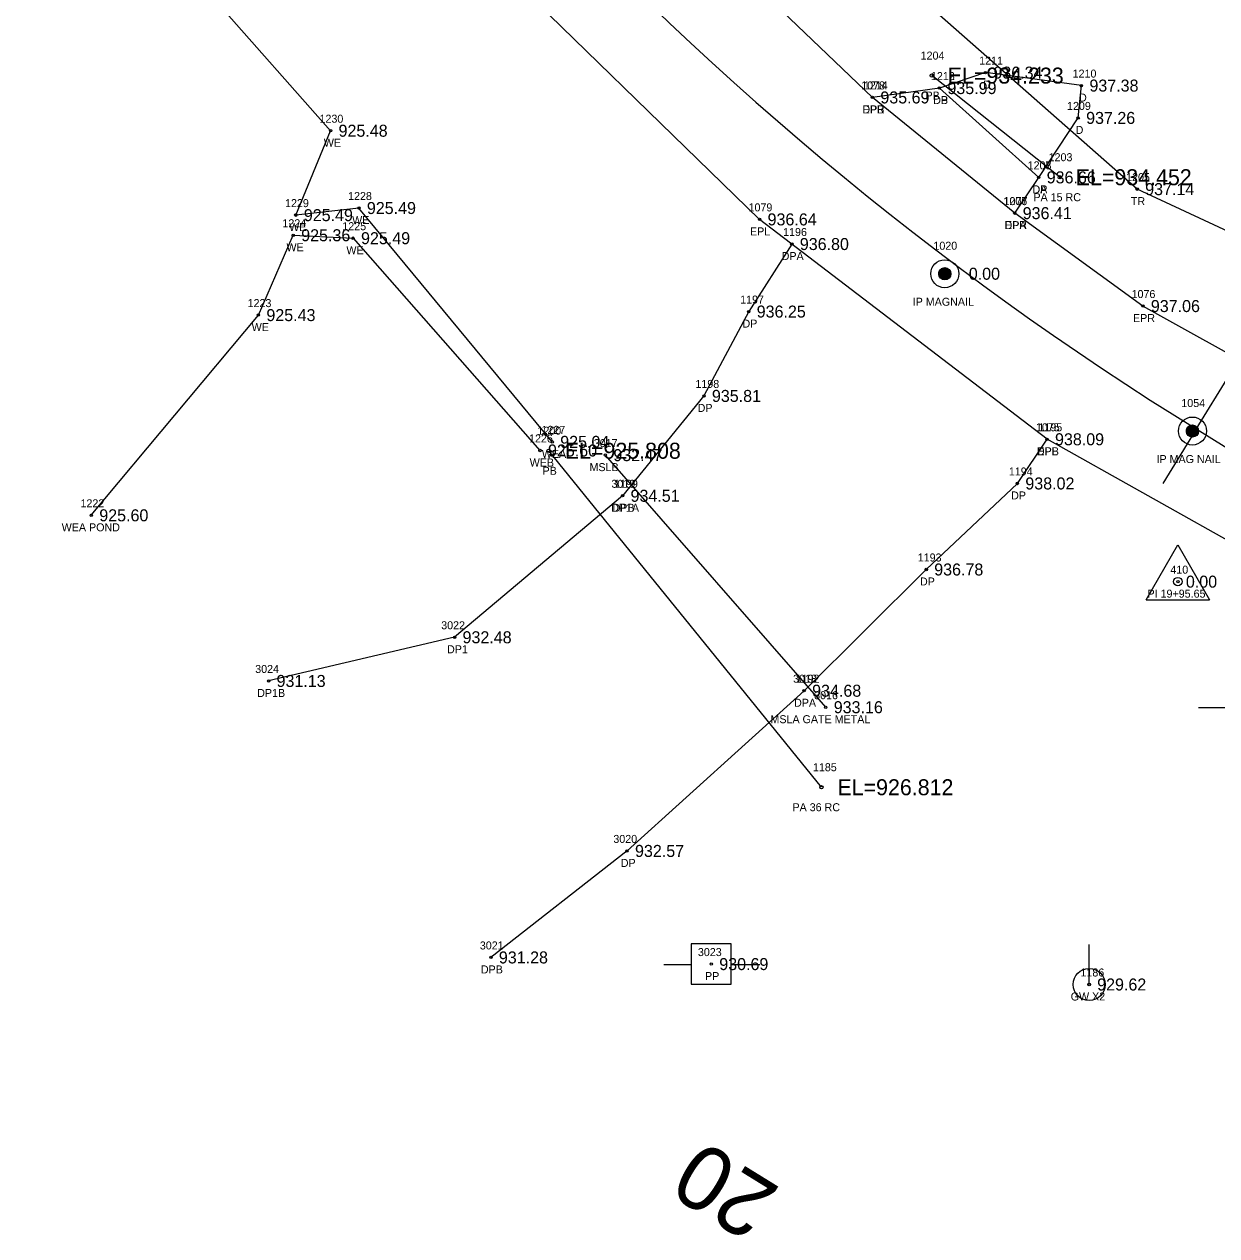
# Model space of a CAD drawing. Extents: x 1528109 to 1531398, y 1157799 to 1162548.
# Drawn here: x 1529980.7 to 1530129.8, y 1159115.4 to 1159266.8 of the extents above; entities that cross this region are included whole.
import ezdxf

# ---------------------------------------------------------------- set-up
doc = ezdxf.new("R2010")
doc.units = 0
for name, color, linetype in [('RD_EX_DR_Pipe', 7, 'Continuous'), ('RD_EX_DR_Pipe_txCode', 7, 'Continuous'), ('RD_EX_Driveway', 7, 'Continuous'), ('RD_EX_Driveway_txCode', 7, 'Continuous'), ('RD_EX_DV_Prop_txCode', 7, 'Continuous'), ('RD_EX_DV_PropPin', 7, 'Continuous'), ('RD_EX_H2O', 7, 'Continuous'), ('RD_EX_H2O_txCode', 7, 'Continuous'), ('RD_EX_Misc', 7, 'Continuous'), ('RD_EX_Misc_txCode', 7, 'Continuous'), ('RD_EX_Road', 7, 'Continuous'), ('RD_EX_Road_txCode', 7, 'Continuous'), ('RD_EX_TX_Driveway_ELEV', 7, 'Continuous'), ('RD_EX_TX_DV_Prop_ELEV', 7, 'Continuous'), ('RD_EX_TX_H2O_ELEV', 7, 'Continuous'), ('RD_EX_TX_Misc_ELEV', 7, 'Continuous'), ('RD_EX_TX_Road_ELEV', 7, 'Continuous'), ('RD_EX_TX_UT_ELEV', 7, 'Continuous'), ('RD_EX_TX_VEG_ELEV', 7, 'Continuous'), ('RD_EX_UT', 7, 'Continuous'), ('RD_EX_UT_txCode', 7, 'Continuous'), ('RD_EX_VEG', 7, 'Continuous'), ('RD_EX_VEG_txCode', 7, 'Continuous'), ('RD_HC_Cl', 7, 'Continuous'), ('RD_HC_Data', 7, 'Continuous'), ('RD_HC_Data_Tic', 7, 'Continuous'), ('RD_HC_Survey_ELEV', 7, 'Continuous'), ('RD_HC_TX_Sta50', 7, 'Continuous'), ('RD_HC_txCode', 7, 'Continuous'), ('RD_SMD_Locator', 7, 'Continuous'), ('RD_TX_Pipe_ElevEX', 7, 'Continuous')]:
    doc.layers.add(name, color=color, linetype=linetype)

msp = doc.modelspace()

# ---------------------------------------------------------------- linework, layer by layer
at = {"layer": 'RD_EX_DR_Pipe'}
for p, q in [((1530110.19, 1159247.64), (1530094.19, 1159260.34)), ((1530080.4, 1159171.41), (1530046.32, 1159213.46))]:
    msp.add_line(p, q, dxfattribs=at)
at = {"layer": 'RD_EX_Driveway'}
for points in [[(1530107.56, 1159247.62), (1530112.49, 1159255.05), (1530112.9, 1159259.09), (1530100.9, 1159260.71), (1530095.15, 1159258.78)], [(1530104.56, 1159243.15), (1530107.56, 1159247.62), (1530095.15, 1159258.78), (1530086.77, 1159257.61)], [(1530076.7, 1159239.29), (1530071.31, 1159230.85), (1530065.71, 1159220.31), (1530055.54, 1159207.83)], [(1530078.24, 1159183.47), (1530093.5, 1159198.62), (1530104.89, 1159209.37), (1530108.6, 1159214.89)], [(1530055.54, 1159207.83), (1530034.54, 1159190.15), (1530011.29, 1159184.69)], [(1530078.24, 1159183.47), (1530056.1, 1159163.45), (1530039.08, 1159150.14)]]:
    msp.add_lwpolyline(points, dxfattribs=at)
at = {"layer": 'RD_EX_DV_PropPin'}
for p, q in [((1530095.61, 1159234.85), (1530095.61, 1159236.31)), ((1530095.65, 1159234.84), (1530095.65, 1159236.32)), ((1530095.68, 1159234.83), (1530095.68, 1159236.33)), ((1530095.72, 1159234.83), (1530095.72, 1159236.33)), ((1530095.75, 1159234.82), (1530095.75, 1159236.34)), ((1530095.79, 1159234.82), (1530095.79, 1159236.34)), ((1530095.82, 1159234.82), (1530095.82, 1159236.34)), ((1530095.86, 1159234.82), (1530095.86, 1159236.34)), ((1530095.89, 1159234.82), (1530095.89, 1159236.34)), ((1530095.93, 1159234.83), (1530095.93, 1159236.33)), ((1530095.96, 1159234.83), (1530095.96, 1159236.33)), ((1530096, 1159234.84), (1530096, 1159236.32)), ((1530096.03, 1159234.85), (1530096.03, 1159236.31)), ((1530095.09, 1159235.38), (1530095.09, 1159235.78)), ((1530095.12, 1159235.28), (1530095.12, 1159235.88)), ((1530095.16, 1159235.21), (1530095.16, 1159235.95)), ((1530095.19, 1159235.15), (1530095.19, 1159236.01)), ((1530095.23, 1159235.11), (1530095.23, 1159236.05)), ((1530095.26, 1159235.07), (1530095.26, 1159236.1)), ((1530095.3, 1159235.03), (1530095.3, 1159236.13)), ((1530095.33, 1159235), (1530095.33, 1159236.16)), ((1530095.37, 1159234.97), (1530095.37, 1159236.19)), ((1530095.4, 1159234.95), (1530095.4, 1159236.21)), ((1530095.44, 1159234.92), (1530095.44, 1159236.24)), ((1530095.47, 1159234.9), (1530095.47, 1159236.26)), ((1530095.51, 1159234.89), (1530095.51, 1159236.27)), ((1530095.54, 1159234.87), (1530095.54, 1159236.29)), ((1530095.58, 1159234.86), (1530095.58, 1159236.3)), ((1530096.07, 1159234.86), (1530096.07, 1159236.3)), ((1530096.1, 1159234.87), (1530096.1, 1159236.29)), ((1530096.14, 1159234.89), (1530096.14, 1159236.27)), ((1530096.17, 1159234.9), (1530096.17, 1159236.26)), ((1530096.21, 1159234.92), (1530096.21, 1159236.24)), ((1530096.24, 1159234.95), (1530096.24, 1159236.21)), ((1530096.28, 1159234.97), (1530096.28, 1159236.19)), ((1530096.31, 1159235), (1530096.31, 1159236.16)), ((1530096.35, 1159235.03), (1530096.35, 1159236.13)), ((1530096.38, 1159235.07), (1530096.38, 1159236.1)), ((1530096.42, 1159235.11), (1530096.42, 1159236.05)), ((1530096.45, 1159235.15), (1530096.45, 1159236.01)), ((1530096.49, 1159235.21), (1530096.49, 1159235.95)), ((1530096.52, 1159235.28), (1530096.52, 1159235.88)), ((1530096.56, 1159235.38), (1530096.56, 1159235.78)), ((1530126.49, 1159215.21), (1530126.49, 1159216.63)), ((1530126.53, 1159215.2), (1530126.53, 1159216.64)), ((1530126.56, 1159215.19), (1530126.56, 1159216.65)), ((1530126.6, 1159215.18), (1530126.6, 1159216.66)), ((1530126.64, 1159215.17), (1530126.64, 1159216.67)), ((1530126.67, 1159215.17), (1530126.67, 1159216.67)), ((1530126.71, 1159215.16), (1530126.71, 1159216.68)), ((1530126.74, 1159215.16), (1530126.74, 1159216.68)), ((1530126.78, 1159215.16), (1530126.78, 1159216.68)), ((1530126.81, 1159215.16), (1530126.81, 1159216.68)), ((1530126.85, 1159215.16), (1530126.85, 1159216.68)), ((1530126.88, 1159215.17), (1530126.88, 1159216.67)), ((1530126.92, 1159215.17), (1530126.92, 1159216.67)), ((1530126.95, 1159215.18), (1530126.95, 1159216.66)), ((1530126.99, 1159215.19), (1530126.99, 1159216.65)), ((1530127.02, 1159215.2), (1530127.02, 1159216.64)), ((1530127.06, 1159215.21), (1530127.06, 1159216.63)), ((1530126.04, 1159215.72), (1530126.04, 1159216.12)), ((1530126.07, 1159215.62), (1530126.07, 1159216.22)), ((1530126.11, 1159215.55), (1530126.11, 1159216.29)), ((1530126.14, 1159215.49), (1530126.14, 1159216.35)), ((1530126.18, 1159215.45), (1530126.18, 1159216.39)), ((1530126.21, 1159215.4), (1530126.21, 1159216.44)), ((1530126.25, 1159215.37), (1530126.25, 1159216.47)), ((1530126.28, 1159215.34), (1530126.28, 1159216.5)), ((1530126.32, 1159215.31), (1530126.32, 1159216.53)), ((1530126.35, 1159215.29), (1530126.35, 1159216.55)), ((1530126.39, 1159215.26), (1530126.39, 1159216.58)), ((1530126.42, 1159215.24), (1530126.42, 1159216.6)), ((1530126.46, 1159215.23), (1530126.46, 1159216.61)), ((1530127.09, 1159215.23), (1530127.09, 1159216.61)), ((1530127.13, 1159215.24), (1530127.13, 1159216.6)), ((1530127.16, 1159215.26), (1530127.16, 1159216.58)), ((1530127.2, 1159215.29), (1530127.2, 1159216.55)), ((1530127.23, 1159215.31), (1530127.23, 1159216.53)), ((1530127.27, 1159215.34), (1530127.27, 1159216.5)), ((1530127.3, 1159215.37), (1530127.3, 1159216.47)), ((1530127.34, 1159215.4), (1530127.34, 1159216.44)), ((1530127.37, 1159215.45), (1530127.37, 1159216.39)), ((1530127.41, 1159215.49), (1530127.41, 1159216.35)), ((1530127.44, 1159215.55), (1530127.44, 1159216.29)), ((1530127.48, 1159215.62), (1530127.48, 1159216.22)), ((1530127.51, 1159215.72), (1530127.51, 1159216.12))]:
    msp.add_line(p, q, dxfattribs=at)
for centre, radius in [((1530095.82, 1159235.58), 1.75), ((1530095.82, 1159235.58), 0.761), ((1530126.78, 1159215.92), 1.75), ((1530126.78, 1159215.92), 0.761)]:
    msp.add_circle(centre, radius, dxfattribs=at)
at = {"layer": 'RD_EX_H2O'}
for points in [[(1530046.75, 1159214.57), (1530022.58, 1159243.79), (1530014.7, 1159242.9), (1530019.04, 1159253.45), (1530004.76, 1159269.6), (1529985.6, 1159289.95), (1529959.08, 1159302.6), (1529953.51, 1159302.02), (1529918.95, 1159284.91)], [(1529989.13, 1159205.39), (1530010.02, 1159230.41), (1530014.37, 1159240.39), (1530021.85, 1159240.02), (1530045.22, 1159213.49)]]:
    msp.add_lwpolyline(points, dxfattribs=at)
at = {"layer": 'RD_EX_Misc'}
msp.add_line((1530080.94, 1159181.41), (1530053.39, 1159212.91), dxfattribs=at)
at = {"layer": 'RD_EX_Road'}
for points in [[(1530337.52, 1159156.44), (1530294.13, 1159166.93), (1530250.93, 1159177.7), (1530204.42, 1159191.5), (1530168.45, 1159204.97), (1530120.58, 1159231.54), (1530104.56, 1159243.15), (1530086.77, 1159257.61), (1530051.98, 1159290.88), (1530019.2, 1159326.18), (1529978.15, 1159378.31), (1529959.68, 1159408.2), (1529942.81, 1159442.34), (1529934.79, 1159460.88), (1529923.22, 1159491.09), (1529910.46, 1159527.95), (1529895.99, 1159570.93), (1529881.69, 1159613.98), (1529856.28, 1159690.67), (1529839.74, 1159739.71), (1529819.57, 1159800.04), (1529788.95, 1159890.99)], [(1530332.28, 1159136.67), (1530288.96, 1159147.06), (1530245.68, 1159158), (1530197.52, 1159172.18), (1530159.1, 1159186.57), (1530108.6, 1159214.89), (1530072.67, 1159242.37), (1530037.12, 1159276.96), (1530005.21, 1159311.5), (1529961.59, 1159366.88), (1529941.79, 1159398.29), (1529924.06, 1159434.11), (1529903.77, 1159484.39), (1529891.44, 1159520.8), (1529876.79, 1159564.7), (1529862.9, 1159606.82), (1529836.94, 1159684.29), (1529820.66, 1159733.09), (1529800.02, 1159794.4), (1529769.54, 1159884.46)]]:
    msp.add_lwpolyline(points, dxfattribs=at)
at = {"layer": 'RD_EX_UT'}
for p, q in [((1530127.55, 1159181.37), (1530131.02, 1159181.37)), ((1530069.12, 1159151.82), (1530064.12, 1159151.82)), ((1530064.12, 1159151.82), (1530064.12, 1159146.82)), ((1530069.12, 1159146.82), (1530069.12, 1159151.82)), ((1530113.87, 1159146.76), (1530113.87, 1159151.76)), ((1530060.69, 1159149.26), (1530064.16, 1159149.26)), ((1530069.05, 1159149.26), (1530072.69, 1159149.26)), ((1530064.12, 1159146.82), (1530069.12, 1159146.82))]:
    msp.add_line(p, q, dxfattribs=at)
msp.add_circle((1530113.87, 1159146.76), 2, dxfattribs=at)
at = {"layer": 'RD_EX_VEG'}
msp.add_lwpolyline([(1530334.72, 1159172.48), (1530202.71, 1159207.61), (1530119.87, 1159246.15), (1530082.28, 1159279.25), (1530129.08, 1159268.9), (1530183.31, 1159274.22)], dxfattribs=at)
at = {"layer": 'RD_HC_Cl'}
msp.add_arc((1530338.63, 1159558.58), 402.39, 222.8065, 256.0174, dxfattribs=at)
at = {"layer": 'RD_HC_Data'}
for p, q in [((1530120.99, 1159194.81), (1530124.96, 1159201.69)), ((1530124.96, 1159201.69), (1530128.93, 1159194.81)), ((1530120.99, 1159194.81), (1530128.93, 1159194.81))]:
    msp.add_line(p, q, dxfattribs=at)
msp.add_circle((1530124.96, 1159197.1), 0.529, dxfattribs=at)
at = {"layer": 'RD_HC_Data_Tic'}
for q in [(1530131.46, 1159222.98), (1530123.06, 1159209.37)]:
    msp.add_line((1530127.26, 1159216.17), q, dxfattribs=at)
at = {"layer": 'RD_SMD_Locator'}
for centre, radius in [((1530094.19, 1159260.34), 0.2), ((1530100.9, 1159260.71), 0.15), ((1530112.9, 1159259.09), 0.15), ((1530086.77, 1159257.61), 0.15), ((1530086.77, 1159257.61), 0.15), ((1530095.15, 1159258.78), 0.15), ((1530095.15, 1159258.78), 0.15), ((1530112.49, 1159255.05), 0.15), ((1530019.04, 1159253.45), 0.15), ((1530107.56, 1159247.62), 0.15), ((1530107.56, 1159247.62), 0.15), ((1530110.19, 1159247.64), 0.2), ((1530119.87, 1159246.15), 0.15), ((1530022.58, 1159243.79), 0.15), ((1530014.7, 1159242.9), 0.15), ((1530072.67, 1159242.37), 0.15), ((1530104.56, 1159243.15), 0.15), ((1530104.56, 1159243.15), 0.15), ((1530014.37, 1159240.39), 0.15), ((1530021.85, 1159240.02), 0.15), ((1530076.7, 1159239.29), 0.15), ((1530095.82, 1159235.58), 0.15), ((1530010.02, 1159230.41), 0.15), ((1530071.31, 1159230.85), 0.15), ((1530120.58, 1159231.54), 0.15), ((1530065.71, 1159220.31), 0.15), ((1530126.78, 1159215.92), 0.15), ((1530045.22, 1159213.49), 0.15), ((1530046.32, 1159213.46), 0.2), ((1530046.75, 1159214.57), 0.15), ((1530108.6, 1159214.89), 0.15), ((1530108.6, 1159214.89), 0.15), ((1530053.39, 1159212.91), 0.15), ((1530104.89, 1159209.37), 0.15), ((1530055.54, 1159207.83), 0.15), ((1530055.54, 1159207.83), 0.15), ((1529989.13, 1159205.39), 0.15), ((1530093.5, 1159198.62), 0.15), ((1530124.96, 1159197.1), 0.15), ((1530034.54, 1159190.15), 0.15), ((1530011.29, 1159184.69), 0.15), ((1530078.24, 1159183.47), 0.15), ((1530078.24, 1159183.47), 0.15), ((1530080.94, 1159181.41), 0.15), ((1530080.4, 1159171.41), 0.2), ((1530056.1, 1159163.45), 0.15), ((1530039.08, 1159150.14), 0.15), ((1530066.63, 1159149.31), 0.15), ((1530113.87, 1159146.76), 0.15)]:
    msp.add_circle(centre, radius, dxfattribs=at)

# ---------------------------------------------------------------- texts
at = {"layer": 'RD_EX_DR_Pipe_txCode'}
for s, p in [('1204', (1530092.8, 1159262.34)), ('PB', (1530093.41, 1159257.34)), ('1203', (1530108.8, 1159249.64)), ('PA 15 RC', (1530106.9, 1159244.64)), ('1200', (1530044.9, 1159215.46)), ('PB', (1530045.54, 1159210.46)), ('1185', (1530079.34, 1159173.41)), ('PA 36 RC', (1530076.78, 1159168.41))]:
    msp.add_text(s, height=1, dxfattribs=at).set_placement(p)
at = {"layer": 'RD_EX_Driveway_txCode'}
for s, p in [('1211', (1530100.12, 1159261.71)), ('1212', (1530094.09, 1159259.78)), ('1213', (1530094.09, 1159259.78)), ('1210', (1530111.8, 1159260.09)), ('1214', (1530085.7, 1159258.61)), ('D', (1530100.6, 1159258.71)), ('DB', (1530094.37, 1159256.78)), ('DP', (1530094.37, 1159256.78)), ('D', (1530112.6, 1159257.09)), ('DPB', (1530085.52, 1159255.61)), ('1209', (1530111.1, 1159256.05)), ('D', (1530112.18, 1159253.05)), ('1207', (1530106.18, 1159248.62)), ('1208', (1530106.18, 1159248.62)), ('DA', (1530106.77, 1159245.62)), ('DP', (1530106.79, 1159245.62)), ('1206', (1530103.15, 1159244.15)), ('1196', (1530075.61, 1159240.29)), ('DPA', (1530103.3, 1159241.15)), ('DPA', (1530075.43, 1159237.29)), ('1197', (1530070.24, 1159231.85)), ('DP', (1530070.53, 1159228.85)), ('1198', (1530064.65, 1159221.31)), ('DP', (1530064.93, 1159218.31)), ('1195', (1530107.53, 1159215.89)), ('DPB', (1530107.34, 1159212.89)), ('1194', (1530103.83, 1159210.37)), ('3019', (1530054.15, 1159208.83)), ('1199', (1530054.48, 1159208.83)), ('DP', (1530104.11, 1159207.37)), ('DP1A', (1530054.11, 1159205.83)), ('DPB', (1530054.29, 1159205.83)), ('1193', (1530092.44, 1159199.62)), ('DP', (1530092.72, 1159196.62)), ('3022', (1530032.87, 1159191.15)), ('DP1', (1530033.6, 1159188.15)), ('3024', (1530009.62, 1159185.69)), ('3018', (1530076.86, 1159184.47)), ('1192', (1530077.18, 1159184.47)), ('DP1B', (1530009.87, 1159182.69)), ('DPA', (1530076.98, 1159181.47)), ('DPA', (1530076.98, 1159181.47)), ('3020', (1530054.39, 1159164.45)), ('DP', (1530055.32, 1159161.45)), ('3021', (1530037.7, 1159151.14)), ('DPB', (1530037.83, 1159148.14))]:
    msp.add_text(s, height=1, dxfattribs=at).set_placement(p)
at = {"layer": 'RD_EX_DV_Prop_txCode'}
for s, p in [('1020', (1530094.4, 1159238.58)), ('IP MAGNAIL', (1530091.81, 1159231.58)), ('1054', (1530125.39, 1159218.92)), ('IP MAG NAIL', (1530122.29, 1159211.92))]:
    msp.add_text(s, height=1, dxfattribs=at).set_placement(p)
at = {"layer": 'RD_EX_H2O_txCode'}
for s, p in [('1230', (1530017.66, 1159254.45)), ('WE', (1530018.2, 1159251.45)), ('1228', (1530021.23, 1159244.79)), ('1229', (1530013.35, 1159243.9)), ('1224', (1530013.02, 1159241.39)), ('WE', (1530021.74, 1159241.79)), ('WE', (1530013.86, 1159240.9)), ('1225', (1530020.51, 1159241.02)), ('WE', (1530013.53, 1159238.39)), ('WE', (1530021.02, 1159238.02)), ('1223', (1530008.67, 1159231.41)), ('WE', (1530009.18, 1159228.41)), ('1226', (1530043.85, 1159214.49)), ('1227', (1530045.41, 1159215.57)), ('WEB', (1530043.93, 1159211.49)), ('WEA', (1530045.45, 1159212.57)), ('1222', (1529987.78, 1159206.39)), ('WEA POND', (1529985.43, 1159203.39))]:
    msp.add_text(s, height=1, dxfattribs=at).set_placement(p)
at = {"layer": 'RD_EX_Misc_txCode'}
for s, p in [('3017', (1530051.94, 1159213.91)), ('MSLB', (1530051.41, 1159210.91)), ('3016', (1530079.49, 1159182.41)), ('MSLA GATE METAL', (1530074.03, 1159179.41))]:
    msp.add_text(s, height=1, dxfattribs=at).set_placement(p)
at = {"layer": 'RD_EX_Road_txCode'}
for s, p in [('1078', (1530085.38, 1159258.61)), ('EPR', (1530085.54, 1159255.61)), ('1079', (1530071.29, 1159243.37)), ('1077', (1530103.18, 1159244.15)), ('EPL', (1530071.47, 1159240.37)), ('EPR', (1530103.34, 1159241.15)), ('1076', (1530119.17, 1159232.54)), ('EPR', (1530119.35, 1159229.54)), ('1075', (1530107.21, 1159215.89)), ('EPL', (1530107.39, 1159212.89))]:
    msp.add_text(s, height=1, dxfattribs=at).set_placement(p)
at = {"layer": 'RD_EX_TX_Driveway_ELEV'}
for s, p in [('936.34', (1530101.9, 1159259.96)), ('935.99', (1530096.15, 1159258.03)), ('935.99', (1530096.15, 1159258.03)), ('937.38', (1530113.9, 1159258.34)), ('935.69', (1530087.77, 1159256.86)), ('937.26', (1530113.49, 1159254.3)), ('936.66', (1530108.56, 1159246.87)), ('936.66', (1530108.56, 1159246.87)), ('936.41', (1530105.56, 1159242.4)), ('936.80', (1530077.7, 1159238.54)), ('936.25', (1530072.31, 1159230.1)), ('935.81', (1530066.71, 1159219.56)), ('938.09', (1530109.6, 1159214.14)), ('938.02', (1530105.89, 1159208.62)), ('934.51', (1530056.54, 1159207.08)), ('934.51', (1530056.54, 1159207.08)), ('936.78', (1530094.5, 1159197.87)), ('932.48', (1530035.54, 1159189.4)), ('931.13', (1530012.29, 1159183.94)), ('934.68', (1530079.24, 1159182.72)), ('934.68', (1530079.24, 1159182.72)), ('932.57', (1530057.1, 1159162.7)), ('931.28', (1530040.08, 1159149.39))]:
    msp.add_text(s, height=1.5, dxfattribs=at).set_placement(p)
at = {"layer": 'RD_EX_TX_DV_Prop_ELEV'}
msp.add_text('0.00', height=1.5, dxfattribs=at).set_placement((1530098.82, 1159234.83))
at = {"layer": 'RD_EX_TX_H2O_ELEV'}
for s, p in [('925.48', (1530020.04, 1159252.7)), ('925.49', (1530023.58, 1159243.04)), ('925.49', (1530015.7, 1159242.15)), ('925.36', (1530015.37, 1159239.64)), ('925.49', (1530022.85, 1159239.27)), ('925.43', (1530011.02, 1159229.66)), ('925.04', (1530047.75, 1159213.82)), ('925.60', (1530046.22, 1159212.74)), ('925.60', (1529990.13, 1159204.64))]:
    msp.add_text(s, height=1.5, dxfattribs=at).set_placement(p)
at = {"layer": 'RD_EX_TX_Misc_ELEV'}
for s, p in [('932.47', (1530054.39, 1159212.16)), ('933.16', (1530081.94, 1159180.66))]:
    msp.add_text(s, height=1.5, dxfattribs=at).set_placement(p)
at = {"layer": 'RD_EX_TX_Road_ELEV'}
for s, p in [('935.69', (1530087.77, 1159256.86)), ('936.41', (1530105.56, 1159242.4)), ('936.64', (1530073.67, 1159241.62)), ('937.06', (1530121.58, 1159230.79)), ('938.09', (1530109.6, 1159214.14))]:
    msp.add_text(s, height=1.5, dxfattribs=at).set_placement(p)
at = {"layer": 'RD_EX_TX_UT_ELEV'}
msp.add_text('929.62', height=1.5, dxfattribs=at).set_placement((1530114.87, 1159146.01))
at = {"layer": 'RD_EX_TX_VEG_ELEV'}
msp.add_text('937.14', height=1.5, dxfattribs=at).set_placement((1530120.87, 1159245.4))
at = {"layer": 'RD_EX_UT_txCode'}
for s, p in [('3023', (1530064.96, 1159150.31)), ('1186', (1530112.78, 1159147.76)), ('PP', (1530065.85, 1159147.31)), ('GW X2', (1530111.56, 1159144.76))]:
    msp.add_text(s, height=1, dxfattribs=at).set_placement(p)
at = {"layer": 'RD_EX_VEG_txCode'}
for s, p in [('1205', (1530118.49, 1159247.15)), ('TR', (1530119.08, 1159244.15))]:
    msp.add_text(s, height=1, dxfattribs=at).set_placement(p)
at = {"layer": 'RD_HC_Survey_ELEV'}
for s, p in [('0.00', (1530125.96, 1159196.35)), ('930.69', (1530067.63, 1159148.56))]:
    msp.add_text(s, height=1.5, dxfattribs=at).set_placement(p)
at = {"layer": 'RD_HC_TX_Sta50'}
msp.add_text('20', height=8, rotation=148.3114, dxfattribs=at).set_placement((1530075.46, 1159121.23))
at = {"layer": 'RD_HC_txCode'}
for s, p in [('410', (1530124.02, 1159198.1)), ('PI 19+95.65', (1530121.16, 1159195.1))]:
    msp.add_text(s, height=1, dxfattribs=at).set_placement(p)
at = {"layer": 'RD_TX_Pipe_ElevEX'}
for s, p in [('EL=934.233', (1530096.19, 1159259.34)), ('EL=934.452', (1530112.19, 1159246.64)), ('EL=925.808', (1530048.32, 1159212.46)), ('EL=926.812', (1530082.4, 1159170.41))]:
    msp.add_text(s, height=2, dxfattribs=at).set_placement(p)

doc.saveas('drawing.dxf')
